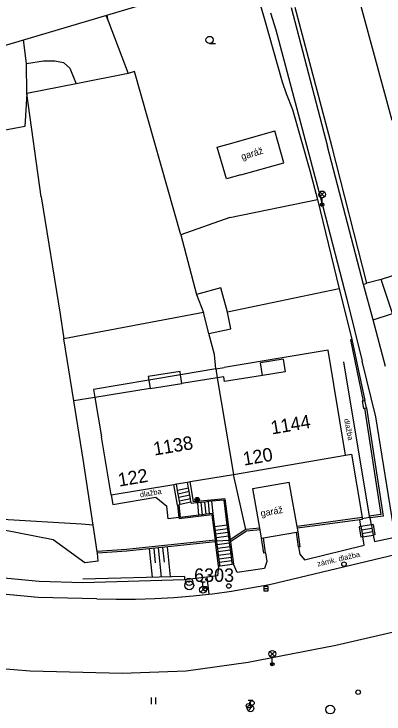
# Model space of a CAD drawing. Extents: x -493753 to -49290, y -1127285 to -112654.
# Drawn here: x -493693 to -493651.7, y -1126830.7 to -1126752.6 of the extents above; entities that cross this region are included whole.
import ezdxf

# ---------------------------------------------------------------- set-up
doc = ezdxf.new("R2010")
doc.units = 0
for name, color, linetype in [('Vrstva 1', 7, 'Continuous'), ('Vrstva 10', 7, 'Continuous'), ('Vrstva 11', 7, 'Continuous'), ('Vrstva 15', 7, 'Continuous'), ('Vrstva 24', 7, 'Continuous'), ('Vrstva 25', 7, 'Continuous'), ('Vrstva 27', 7, 'Continuous'), ('Vrstva 28', 7, 'Continuous'), ('Vrstva 31', 7, 'Continuous'), ('Vrstva 33', 7, 'Continuous'), ('Vrstva 36', 7, 'Continuous'), ('Vrstva 40', 7, 'Continuous'), ('Vrstva 41', 7, 'Continuous'), ('Vrstva 43', 7, 'Continuous'), ('Vrstva 44', 7, 'Continuous'), ('Vrstva 5', 7, 'Continuous'), ('Vrstva 60', 7, 'Continuous'), ('Vrstva 63', 7, 'Continuous'), ('Vrstva 7', 7, 'Continuous'), ('Vrstva 8', 7, 'Continuous')]:
    doc.layers.add(name, color=color, linetype=linetype)

msp = doc.modelspace()

# ---------------------------------------------------------------- linework, layer by layer
at = {"layer": 'Vrstva 1'}
msp.add_line((-492950.39, -1126535.73), (-493753.129, -1126773.634), dxfattribs=at)
at = {"layer": 'Vrstva 10'}
for p, q in [((-493662.04, -1126751.88), (-493658, -1126767.38)), ((-493682.725, -1126752.769), (-493682.49, -1126753.36)), ((-493656.2, -1126791.44), (-493653.33, -1126808.65)), ((-493652.6, -1126797.56), (-493654.12, -1126791.36)), ((-493650.48, -1126810.75), (-493652.6, -1126797.56)), ((-493655.97, -1126801.83), (-493655.32, -1126801.72)), ((-493655.32, -1126801.72), (-493654.14, -1126808.81)), ((-493672.94, -1126807.05), (-493673.32, -1126804.79)), ((-493682.14, -1126806.27), (-493681.96, -1126807.35)), ((-493681.96, -1126807.35), (-493677.14, -1126806.54)), ((-493677.14, -1126806.54), (-493675.94, -1126807.53)), ((-493669.45, -1126806.7), (-493672.94, -1126807.05)), ((-493669.45, -1126806.7), (-493668.86, -1126811.29)), ((-493675.77, -1126808.95), (-493675.94, -1126807.53)), ((-493674.57, -1126808.8), (-493675.77, -1126808.95)), ((-493670.88, -1126808.51), (-493674.55, -1126808.96)), ((-493670.51, -1126811.33), (-493670.88, -1126808.51)), ((-493653.09, -1126809.61), (-493653.22, -1126808.84)), ((-493654.26, -1126809.81), (-493654.4, -1126809.05)), ((-493652.89, -1126809.58), (-493653.09, -1126809.61)), ((-493652.89, -1126809.58), (-493652.69, -1126810.73)), ((-493654.26, -1126809.81), (-493654.46, -1126809.85)), ((-493654.46, -1126809.85), (-493654.26, -1126811)), ((-493654.06, -1126810.96), (-493654.26, -1126811)), ((-493653.9, -1126811.9), (-493654.06, -1126810.96)), ((-493652.69, -1126810.73), (-493652.89, -1126810.76)), ((-493652.89, -1126810.76), (-493652.76, -1126811.49)), ((-493652.76, -1126811.49), (-493650.81, -1126811.08)), ((-493661.24, -1126812.09), (-493661.09, -1126812.88)), ((-493660.57, -1126813.54), (-493653.9, -1126811.9)), ((-493664.91, -1126812.75), (-493664.75, -1126813.72)), ((-493661.09, -1126812.88), (-493660.57, -1126813.54)), ((-493664.46, -1126816.26), (-493650.3, -1126812.9)), ((-493670.14, -1126814.24), (-493670.26, -1126815.32)), ((-493668.08, -1126814.94), (-493668.5, -1126814.02)), ((-493664.75, -1126813.72), (-493665.02, -1126814.48)), ((-493665.02, -1126814.48), (-493668.08, -1126814.94)), ((-493673.96, -1126815.37), (-493685.3, -1126815.68)), ((-493673.95, -1126815.77), (-493685.29, -1126816.08)), ((-493673.96, -1126815.37), (-493673.95, -1126815.77)), ((-493657.08, -1126823.04), (-493650.28, -1126821.5)), ((-493666.84, -1126824.96), (-493657.08, -1126823.04)), ((-493700.59, -1126825.11), (-493691.19, -1126825.92)), ((-493673.76, -1126825.92), (-493666.84, -1126824.96)), ((-493691.19, -1126825.92), (-493680.91, -1126826.17)), ((-493680.91, -1126826.17), (-493673.76, -1126825.92))]:
    msp.add_line(p, q, dxfattribs=at)
for points in [[(-493664.35, -1126752.47), (-493663.77, -1126754.35), (-493658.46, -1126774.22), (-493655.85, -1126784.41), (-493654.12, -1126791.36)], [(-493653.96, -1126782.8), (-493658, -1126767.38)], [(-493653.96, -1126782.8), (-493653.59, -1126782.64)], [(-493652.88, -1126786.74), (-493653.96, -1126782.8)], [(-493652.88, -1126786.74), (-493650.73, -1126786.02)], [(-493651.51, -1126791.93), (-493652.88, -1126786.74)], [(-493674.57, -1126808.8), (-493674.55, -1126808.96)], [(-493668.86, -1126811.29), (-493668.82, -1126811.51)], [(-493670.14, -1126814.24), (-493670.49, -1126811.53), (-493670.51, -1126811.33)], [(-493668.82, -1126811.51), (-493668.5, -1126814.02)], [(-493685.29, -1126816.08), (-493690.16, -1126815.94), (-493698.05, -1126815.2), (-493703.45, -1126814.33)], [(-493683.74, -1126817.89), (-493690.29, -1126817.73), (-493698.23, -1126816.99), (-493705.92, -1126815.68), (-493710.74, -1126814.64)], [(-493670.26, -1126815.32), (-493671.47, -1126815.47), (-493673.95, -1126815.77)], [(-493683.74, -1126817.89), (-493681.59, -1126817.93), (-493679.44, -1126817.92), (-493677.28, -1126817.85), (-493675.13, -1126817.73), (-493672.98, -1126817.54), (-493671.24, -1126817.35), (-493670.83, -1126817.31), (-493668.7, -1126817.01), (-493666.57, -1126816.66), (-493664.46, -1126816.26)]]:
    msp.add_lwpolyline(points, dxfattribs=at)
at = {"layer": 'Vrstva 11'}
for p, q in [((-493670.46, -1126792.22), (-493674.39, -1126792.88)), ((-493670.46, -1126792.22), (-493669.52, -1126792.06)), ((-493670.46, -1126792.22), (-493670.3, -1126793.2)), ((-493674.39, -1126792.88), (-493677.95, -1126793.47)), ((-493670.3, -1126793.2), (-493668.5, -1126803.98)), ((-493677.95, -1126793.47), (-493684.11, -1126794.5)), ((-493684.11, -1126794.5), (-493683.96, -1126795.39)), ((-493683.96, -1126795.39), (-493683.23, -1126799.78)), ((-493674.75, -1126807.41), (-493675.14, -1126805.1)), ((-493673.5, -1126805.52), (-493674.72, -1126805.78)), ((-493673.43, -1126805.91), (-493674.65, -1126806.18)), ((-493673.37, -1126806.31), (-493674.59, -1126806.57)), ((-493673.3, -1126806.7), (-493674.52, -1126806.96)), ((-493673.24, -1126807.1), (-493674.45, -1126807.36)), ((-493673.24, -1126807.1), (-493673.21, -1126807.25)), ((-493672.92, -1126807.2), (-493673.21, -1126807.25)), ((-493672.34, -1126808.54), (-493672.48, -1126807.15)), ((-493671.94, -1126808.49), (-493672.08, -1126807.11)), ((-493671.54, -1126808.44), (-493671.68, -1126807.07)), ((-493671.15, -1126808.39), (-493671.28, -1126807.03)), ((-493670.75, -1126808.34), (-493670.89, -1126806.99)), ((-493669.22, -1126809.67), (-493670.55, -1126809.85)), ((-493653.09, -1126809.61), (-493654.26, -1126809.81)), ((-493669.16, -1126810.07), (-493670.5, -1126810.25)), ((-493669.11, -1126810.47), (-493670.45, -1126810.65)), ((-493654.2, -1126810.18), (-493653.03, -1126809.97)), ((-493654.13, -1126810.57), (-493652.96, -1126810.37)), ((-493669.06, -1126810.87), (-493670.4, -1126811.05)), ((-493654.06, -1126810.96), (-493652.89, -1126810.76)), ((-493668.96, -1126811.66), (-493670.29, -1126811.84)), ((-493668.91, -1126812.06), (-493670.24, -1126812.24)), ((-493668.86, -1126812.45), (-493670.19, -1126812.63)), ((-493668.8, -1126812.85), (-493670.14, -1126813.03)), ((-493668.75, -1126813.25), (-493670.09, -1126813.43)), ((-493668.7, -1126813.64), (-493670.04, -1126813.82)), ((-493669.99, -1126814.22), (-493670.14, -1126814.24)), ((-493668.65, -1126814.04), (-493669.99, -1126814.22)), ((-493668.5, -1126814.02), (-493668.65, -1126814.04)), ((-493671.47, -1126815.47), (-493671.24, -1126817.35))]:
    msp.add_line(p, q, dxfattribs=at)
for points in [[(-493650.76, -1126764.5), (-493656.099, -1126744.878)], [(-493682.49, -1126753.36), (-493680.23, -1126759.25)], [(-493691.59, -1126758.14), (-493691.91, -1126755.491)], [(-493691.59, -1126758.14), (-493689.7, -1126757.83), (-493688.42, -1126757.83), (-493687.46, -1126758.02), (-493686.77, -1126758.66), (-493686.06, -1126760.39)], [(-493691.55, -1126761.46), (-493691.59, -1126758.14)], [(-493680.23, -1126759.25), (-493686.06, -1126760.39)], [(-493679.54, -1126759.02), (-493680.23, -1126759.25)], [(-493674.37, -1126777.25), (-493679.54, -1126759.02)], [(-493686.06, -1126760.39), (-493691.55, -1126761.46)], [(-493691.55, -1126761.46), (-493691.76, -1126765.16)], [(-493689.94, -1126773), (-493691.55, -1126761.46)], [(-493691.76, -1126765.16), (-493700.35, -1126766.77)], [(-493670.29, -1126767.46), (-493668.67, -1126767)], [(-493669.27, -1126771.01), (-493670.29, -1126767.46)], [(-493667.67, -1126770.56), (-493669.27, -1126771.01)], [(-493689.94, -1126773), (-493687.85, -1126786.1)], [(-493668.89, -1126775.32), (-493674.37, -1126777.25)], [(-493674.37, -1126777.25), (-493672.61, -1126783.9)], [(-493669.88, -1126783.17), (-493672.61, -1126783.9)], [(-493669.16, -1126785.89), (-493669.88, -1126783.17)], [(-493672.61, -1126783.9), (-493671.85, -1126785.93)], [(-493656.68, -1126783.26), (-493669.16, -1126785.89)], [(-493687.85, -1126786.1), (-493687.41, -1126788.86)], [(-493671.85, -1126785.93), (-493687.41, -1126788.86)], [(-493671.23, -1126788.27), (-493671.85, -1126785.93)], [(-493668.77, -1126787.75), (-493669.16, -1126785.89)], [(-493671.23, -1126788.27), (-493668.77, -1126787.75)], [(-493670.61, -1126790.6), (-493671.23, -1126788.27)], [(-493686.31, -1126795.79), (-493687.41, -1126788.86)], [(-493670.46, -1126792.22), (-493670.61, -1126790.6)], [(-493662.93, -1126791.12), (-493665.48, -1126791.53)], [(-493665.25, -1126792.95), (-493665.48, -1126791.53)], [(-493662.93, -1126791.12), (-493662.7, -1126792.54)], [(-493674.45, -1126792.5), (-493678.02, -1126793.07)], [(-493674.39, -1126792.88), (-493674.45, -1126792.5)], [(-493662.7, -1126792.54), (-493665.25, -1126792.95)], [(-493678.02, -1126793.07), (-493677.95, -1126793.47)], [(-493674.24, -1126793.83), (-493674.39, -1126792.88)], [(-493670.3, -1126793.2), (-493674.24, -1126793.83)], [(-493669.58, -1126793.08), (-493670.3, -1126793.2)], [(-493669.49, -1126793.63), (-493669.58, -1126793.08)], [(-493665.25, -1126792.95), (-493669.49, -1126793.63)], [(-493677.95, -1126793.47), (-493677.8, -1126794.41)], [(-493677.8, -1126794.41), (-493674.24, -1126793.83)], [(-493677.8, -1126794.41), (-493683.96, -1126795.39)], [(-493683.96, -1126795.39), (-493686.31, -1126795.79)], [(-493685.28, -1126802.28), (-493686.31, -1126795.79)], [(-493684.15, -1126809.67), (-493685.28, -1126802.28)], [(-493674.45, -1126807.36), (-493674.52, -1126806.96), (-493674.59, -1126806.57), (-493674.65, -1126806.18), (-493674.72, -1126805.78), (-493674.84, -1126805.05)], [(-493673.24, -1126807.1), (-493673.3, -1126806.7), (-493673.37, -1126806.31), (-493673.43, -1126805.91), (-493673.5, -1126805.52), (-493673.62, -1126804.84)], [(-493688.6, -1126811.29), (-493717.66, -1126805.58)], [(-493674.75, -1126807.41), (-493674.57, -1126808.8)], [(-493674.45, -1126807.36), (-493674.59, -1126807.38), (-493674.42, -1126808.79)], [(-493669.58, -1126806.86), (-493670.89, -1126806.99), (-493671.28, -1126807.03), (-493671.68, -1126807.07), (-493672.08, -1126807.11), (-493672.48, -1126807.15), (-493672.92, -1126807.2)], [(-493669.58, -1126806.86), (-493669.22, -1126809.67), (-493669.16, -1126810.07), (-493669.11, -1126810.47), (-493669.06, -1126810.87), (-493669.01, -1126811.31), (-493668.96, -1126811.66), (-493668.91, -1126812.06), (-493668.86, -1126812.45), (-493668.8, -1126812.85), (-493668.75, -1126813.25), (-493668.7, -1126813.64), (-493668.65, -1126814.04)], [(-493670.75, -1126808.34), (-493671.15, -1126808.39), (-493671.54, -1126808.44), (-493671.94, -1126808.49), (-493672.34, -1126808.54), (-493674.42, -1126808.79)], [(-493670.4, -1126811.05), (-493670.45, -1126810.65), (-493670.5, -1126810.25), (-493670.55, -1126809.85), (-493670.75, -1126808.34)], [(-493685.46, -1126809.55), (-493694.28, -1126809.03)], [(-493653.09, -1126809.61), (-493653.03, -1126809.97), (-493652.96, -1126810.37), (-493652.89, -1126810.76)], [(-493654.26, -1126809.81), (-493654.2, -1126810.18), (-493654.13, -1126810.57), (-493654.06, -1126810.96)], [(-493685.06, -1126813.86), (-493688.6, -1126811.29)], [(-493670.29, -1126811.84), (-493670.35, -1126811.41), (-493670.4, -1126811.05)], [(-493669.99, -1126814.22), (-493670.04, -1126813.82), (-493670.09, -1126813.43), (-493670.14, -1126813.03), (-493670.19, -1126812.63), (-493670.24, -1126812.24), (-493670.29, -1126811.84)], [(-493683.58, -1126813.67), (-493683.68, -1126812.78)], [(-493683.58, -1126813.67), (-493685.06, -1126813.86)]]:
    msp.add_lwpolyline(points, dxfattribs=at)
at = {"layer": 'Vrstva 15'}
for p, q in [((-493675.51, -1126815.41), (-493675.86, -1126812.09)), ((-493677.51, -1126815.47), (-493677.85, -1126812.3)), ((-493677.18, -1126813.85), (-493677.35, -1126812.25)), ((-493676.51, -1126815.44), (-493676.85, -1126812.2)), ((-493676.18, -1126813.79), (-493676.36, -1126812.15))]:
    msp.add_line(p, q, dxfattribs=at)
at = {"layer": 'Vrstva 24'}
msp.add_line((-493654.13, -1126795.82), (-493653.96, -1126796.63), dxfattribs=at)
for points in [[(-493653.64, -1126796.56), (-493653.81, -1126795.75), (-493654.02, -1126795.8), (-493654.13, -1126795.82)], [(-493653.96, -1126796.63), (-493653.86, -1126796.61), (-493653.64, -1126796.56)]]:
    msp.add_lwpolyline(points, dxfattribs=at)
at = {"layer": 'Vrstva 25'}
for radius in [0.25, 0.158, 0.05]:
    msp.add_circle((-493672.54, -1126806.81), radius, dxfattribs=at)
at = {"layer": 'Vrstva 27'}
msp.add_line((-493665.11, -1126816.74), (-493664.61, -1126816.74), dxfattribs=at)
msp.add_lwpolyline([(-493665.11, -1126816.99), (-493664.61, -1126816.99), (-493664.61, -1126816.49), (-493665.11, -1126816.49)], close=True, dxfattribs=at)
for centre in [(-493673.43, -1126816.37), (-493657.69, -1126830.23)]:
    msp.add_circle(centre, 0.5, dxfattribs=at)
at = {"layer": 'Vrstva 28'}
for p, q in [((-493672.14, -1126815.96), (-493671.64, -1126815.96)), ((-493671.89, -1126816.485), (-493671.89, -1126815.96)), ((-493672.155, -1126817.125), (-493671.625, -1126816.595)), ((-493666.84, -1126829.2), (-493666.34, -1126829.2)), ((-493666.59, -1126829.725), (-493666.59, -1126829.2)), ((-493666.855, -1126830.365), (-493666.325, -1126829.835))]:
    msp.add_line(p, q, dxfattribs=at)
for centre, radius in [((-493656.15, -1126814), 0.25), ((-493671.89, -1126816.86), 0.375), ((-493671.64, -1126816.74), 0.25), ((-493669.01, -1126816.45), 0.25), ((-493666.42, -1126829.5), 0.25), ((-493666.82, -1126829.81), 0.25), ((-493666.59, -1126830.1), 0.375)]:
    msp.add_circle(centre, radius, dxfattribs=at)
at = {"layer": 'Vrstva 31'}
msp.add_circle((-493654.57, -1126828.3), 0.25, dxfattribs=at)
at = {"layer": 'Vrstva 33'}
for p, q in [((-493658.855, -1126772.465), (-493658.325, -1126772.995)), ((-493658.855, -1126772.995), (-493658.325, -1126772.465)), ((-493658.59, -1126773.88), (-493658.59, -1126773.105)), ((-493664.415, -1126823.765), (-493663.885, -1126824.295)), ((-493664.415, -1126824.295), (-493663.885, -1126823.765)), ((-493664.15, -1126825.18), (-493664.15, -1126824.405))]:
    msp.add_line(p, q, dxfattribs=at)
for centre, radius in [((-493658.59, -1126772.73), 0.375), ((-493658.59, -1126773.88), 0.19), ((-493658.59, -1126773.88), 0.05), ((-493664.15, -1126824.03), 0.375), ((-493664.15, -1126825.18), 0.19), ((-493664.15, -1126825.18), 0.05)]:
    msp.add_circle(centre, radius, dxfattribs=at)
at = {"layer": 'Vrstva 36'}
for p, q in [((-493671.152, -1126755.9), (-493670.502, -1126755.897)), ((-493677.65, -1126829.64), (-493677.65, -1126828.89)), ((-493677.15, -1126829.64), (-493677.15, -1126828.89))]:
    msp.add_line(p, q, dxfattribs=at)
msp.add_circle((-493671.152, -1126755.497), 0.403, dxfattribs=at)
at = {"layer": 'Vrstva 5'}
for p, q in [((-493668.67, -1126767), (-493663.86, -1126765.65)), ((-493667.67, -1126770.56), (-493662.86, -1126769.21)), ((-493647.26, -1126780.65), (-493652, -1126782.24)), ((-493657.92, -1126790.13), (-493669.52, -1126792.06)), ((-493655.97, -1126801.83), (-493657.92, -1126790.13)), ((-493682.14, -1126806.27), (-493683.23, -1126799.78)), ((-493668.5, -1126803.98), (-493655.97, -1126801.83)), ((-493666.32, -1126805.57), (-493662.26, -1126804.85))]:
    msp.add_line(p, q, dxfattribs=at)
for points in [[(-493662.86, -1126769.21), (-493663.86, -1126765.65)], [(-493650.73, -1126786.02), (-493652, -1126782.24)], [(-493682.14, -1126806.27), (-493675.14, -1126805.1), (-493674.84, -1126805.05), (-493673.62, -1126804.84), (-493673.32, -1126804.79), (-493668.5, -1126803.98)], [(-493661.28, -1126810.39), (-493661.35, -1126810), (-493661.38, -1126809.8), (-493662.26, -1126804.85)], [(-493665.34, -1126811.11), (-493665.5, -1126810.18), (-493665.54, -1126809.98), (-493666.32, -1126805.57)], [(-493665.34, -1126811.11), (-493665.14, -1126811.08), (-493661.47, -1126810.43), (-493661.28, -1126810.39)]]:
    msp.add_lwpolyline(points, dxfattribs=at)
at = {"layer": 'Vrstva 60'}
msp.add_line((-493125, -1126587.478), (-493750, -1126772.707), dxfattribs=at)
at = {"layer": 'Vrstva 63'}
for radius in [0.412, 0.05]:
    msp.add_circle((-493673.44, -1126815.98), radius, dxfattribs=at)
at = {"layer": 'Vrstva 7'}
for p, q in [((-493666.46, -1126748.24), (-493665.05, -1126753.08)), ((-493657.51, -1126767.3), (-493661.6, -1126751.89)), ((-493682.49, -1126753.36), (-493682.582, -1126752.727)), ((-493653.59, -1126782.64), (-493657.51, -1126767.3)), ((-493668.89, -1126775.32), (-493659.09, -1126773.32)), ((-493652, -1126782.24), (-493653.59, -1126782.64)), ((-493655.28, -1126788.92), (-493655.41, -1126788.95)), ((-493655.41, -1126788.95), (-493654.02, -1126795.8)), ((-493655.28, -1126788.92), (-493653.81, -1126795.75)), ((-493653.86, -1126796.61), (-493652.02, -1126808.47)), ((-493653.64, -1126796.56), (-493651.79, -1126808.64)), ((-493667.12, -1126810.13), (-493668.5, -1126803.98)), ((-493654.14, -1126808.81), (-493661.38, -1126809.8)), ((-493652.02, -1126808.47), (-493653.33, -1126808.65)), ((-493667.12, -1126810.13), (-493668.86, -1126811.29)), ((-493667.05, -1126810.32), (-493668.82, -1126811.51)), ((-493665.54, -1126809.98), (-493667.12, -1126810.13)), ((-493665.5, -1126810.18), (-493667.05, -1126810.32)), ((-493661.24, -1126812.09), (-493661.47, -1126810.43)), ((-493661.04, -1126812.06), (-493661.28, -1126810.39)), ((-493665.11, -1126812.78), (-493665.34, -1126811.11)), ((-493664.91, -1126812.75), (-493665.14, -1126811.08)), ((-493670.51, -1126811.33), (-493680.41, -1126812.37)), ((-493661.04, -1126812.06), (-493661.24, -1126812.09)), ((-493683.68, -1126812.78), (-493683.71, -1126812.58)), ((-493664.91, -1126812.75), (-493665.11, -1126812.78))]:
    msp.add_line(p, q, dxfattribs=at)
for points in [[(-493665.05, -1126753.08), (-493663.06, -1126760.18)], [(-493662.61, -1126761.49), (-493661.9, -1126763.27)], [(-493659.95, -1126770.05), (-493659.09, -1126773.32)], [(-493659.09, -1126773.32), (-493656.68, -1126783.26), (-493656.33, -1126784.71)], [(-493654.14, -1126808.81), (-493654.12, -1126808.91), (-493654.11, -1126809.01)], [(-493653.33, -1126808.65), (-493653.31, -1126808.75), (-493653.3, -1126808.85)], [(-493651.79, -1126808.64), (-493653.22, -1126808.84), (-493653.3, -1126808.85)], [(-493683.71, -1126812.58), (-493684.15, -1126809.67), (-493685.46, -1126809.55)], [(-493654.11, -1126809.01), (-493654.4, -1126809.05), (-493661.35, -1126810)], [(-493670.49, -1126811.53), (-493680.39, -1126812.57)], [(-493680.41, -1126812.37), (-493683.71, -1126812.58)], [(-493680.39, -1126812.57), (-493683.68, -1126812.78)]]:
    msp.add_lwpolyline(points, dxfattribs=at)
at = {"layer": 'Vrstva 8'}
msp.add_line((-493654.12, -1126808.91), (-493653.31, -1126808.75), dxfattribs=at)
for points in [[(-493663.06, -1126760.18), (-493662.61, -1126761.49)], [(-493661.9, -1126763.27), (-493659.95, -1126770.05)], [(-493656.33, -1126784.71), (-493655.28, -1126788.92)], [(-493670.35, -1126811.41), (-493669.01, -1126811.31), (-493668.86, -1126811.29)]]:
    msp.add_lwpolyline(points, dxfattribs=at)

# ---------------------------------------------------------------- texts
at = {"layer": 'Vrstva 40'}
for s, rotation, p in [('dlažba', 281.62481, (-493656.162, -1126797.836)), ('dlažba', 9.46833, (-493678.885, -1126806.555)), ('zámk. dlažba', 13.34873, (-493659.071, -1126814.28))]:
    msp.add_text(s, height=0.6, rotation=rotation, dxfattribs=at).set_placement(p)
at = {"layer": 'Vrstva 41'}
for rotation, p in [(17.01771, (-493667.506, -1126768.899)), (10.05628, (-493665.392, -1126808.716))]:
    msp.add_text('garáž', height=0.75, rotation=rotation, dxfattribs=at).set_placement(p)
at = {"layer": 'Vrstva 43'}
for s, rotation, p in [('1144', 9.73677, (-493664.195, -1126799.537)), ('1138', 9.53387, (-493677.309, -1126801.888))]:
    msp.add_text(s, height=1.5, rotation=rotation, dxfattribs=at).set_placement(p)
at = {"layer": 'Vrstva 44'}
for s, rotation, p in [('120', 9.73677, (-493667.31, -1126803.012)), ('122', 9.53387, (-493681.249, -1126805.357))]:
    msp.add_text(s, height=1.5, rotation=rotation, dxfattribs=at).set_placement(p)
at = {"layer": 'Vrstva 63'}
msp.add_text(' 6303', height=1.5, dxfattribs=at).set_placement((-493673.44, -1126815.98))

doc.saveas('drawing.dxf')
